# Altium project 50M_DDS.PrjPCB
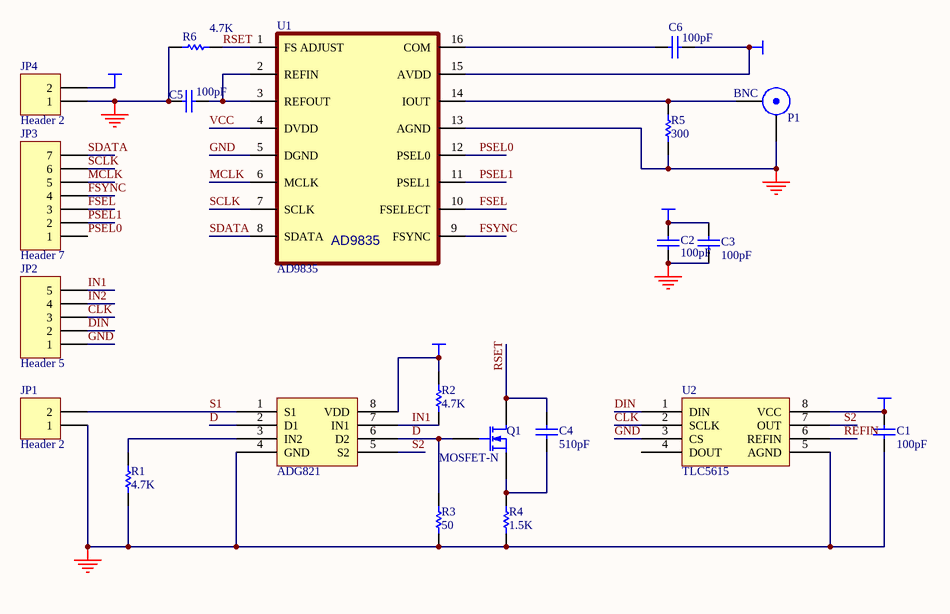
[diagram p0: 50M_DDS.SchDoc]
1 sheet, 21 parts. Net scope: global (net labels, ports and power ports of the same name join across sheets).
Board file: 50M_DDS.PcbDoc

## Sheet 50M_DDS.SchDoc
size B

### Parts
C1  100pF  [CC2012-0805]
C2  100pF  [CC2012-0805]
C3  100pF  [CC2012-0805]
C4  510pF  [CC2012-0805]
C5  100pF  [CC2012-0805]
C6  100pF  [CC2012-0805]
JP1  Header 2  [HDR1X2]
JP2  Header 5  [HDR1X5]
JP3  Header 7  [HDR1X7]
JP4  Header 2  [HDR1X2]
P1  BNC  [BNC_RA CON]
Q1  MOSFET-N  [BCY-W3/H.8]
R1  4.7K  [R2012-0805]
R2  4.7K  [R2012-0805]
R3  50  [R2012-0805]
R4  1.5K  [R2012-0805]
R5  300  [R2012-0805]
R6  4.7K  [R2012-0805]
U1  AD9835  [TSSO5X6-G16]
U2  TLC5615  [SO-G8]
  ADG821  [TSSO3X5-G8/X.35]

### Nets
GND: C1.1 C2.1 C3.1 C5.1 JP1.1 JP2.1 JP4.1 P1.1(X) R1.2 R3.1 R4.1 R5.1 R6.1 U1.5(DGND) U1.13(AGND) U2.3(CS) U2.5(AGND) .4(GND)
VCC: C1.2 C2.2 C3.2 C6.1 JP4.2 R2.2 U1.4(DVDD) U1.15(AVDD) U2.8(VCC) .8(VDD)
CLK: JP2.3 U2.2(SCLK)
D: Q1.2(G) R3.2 .2(D1) .6(D2)
DIN: JP2.2 U2.1(DIN)
FSEL: JP3.3 U1.10(FSELECT)
FSYNC: JP3.4 U1.9(FSYNC)
IN1: JP2.5 R2.1 .7(IN1)
IN2: JP2.4
MCLK: JP3.5 U1.6(MCLK)
PSEL0: JP3.1 U1.12(PSEL0)
PSEL1: JP3.2 U1.11(PSEL1)
REFIN: U2.6(REFIN)
RSET: C4.2 Q1.1(D) R6.2 U1.1(FS_ADJUST)
S1: JP1.2 .1(S1)
S2: U2.7(OUT) .5(S2)
SCLK: JP3.6 U1.7(SCLK)
SDATA: JP3.7 U1.8(SDATA)
NetC4_1: C4.1 Q1.3(S) R4.2
NetC5_2: C5.2 U1.2(REFIN) U1.3(REFOUT)
NetC6_2: C6.2 U1.16(COM)
NetP1_2: P1.2(Y) R5.2 U1.14(IOUT)
NetR1_1: R1.1 .3(IN2)

Not connected (* = marked no-connect by the designer): U2 4(DOUT)

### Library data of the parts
C1-C6 = Cap: Capacitor; Manufacturer: Generic Components; Class I: Passive
JP1 JP4 = Header 2: Header, 2-Pin; Manufacturer: Generic Components; Class I: Connector
JP2 = Header 5: Header, 5-Pin; Manufacturer: Generic Components; Class I: Connector
JP3 = Header 7: Header, 7-Pin; Manufacturer: Generic Components; Class I: Connector
P1 = BNC: BNC Elbow Connector; Manufacturer: Generic Components; Class II: RF Coaxial
Q1 = MOSFET-N: N-Channel MOSFET; Manufacturer: Generic Components; Class I: Discrete; Class II: MOSFET - Low Power
R1-R6 = Res1: Resistor; Manufacturer: Generic Components; Class I: Passive
U1 = AD9835: 50 MHz CMOS / Complete DDS
U2 = TLC5615: 10bit DA Convertor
